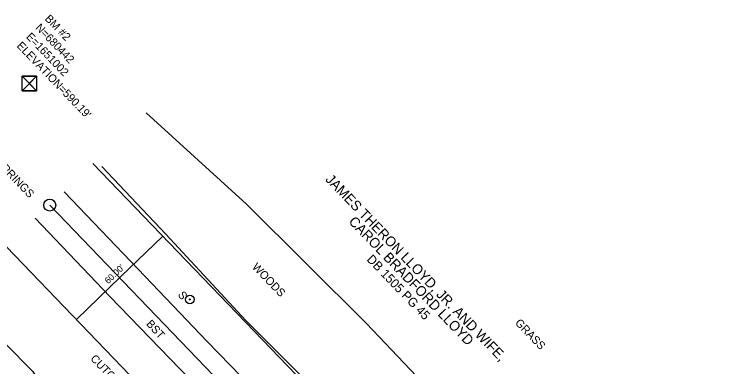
# Model space of a CAD drawing. Extents: x 1650735 to 1651711, y 679647 to 680525.
# Drawn here: x 1650994.6 to 1651353.2, y 680300.3 to 680476.3 of the extents above; entities that cross this region are included whole.
import ezdxf

# ---------------------------------------------------------------- set-up
doc = ezdxf.new("R2010")
doc.units = 0
for name, color, linetype in [('CTL Bench Mark CELL', 7, 'Continuous'), ('CTL Bench Mark Text', 7, 'Continuous'), ('Exist Horizontal Alignment', 7, 'Continuous'), ('Exist Horizontal Alignment Point', 7, 'Continuous'), ('Exist Other Culture Sign CELL', 7, 'Continuous'), ('Exist Other Culture Sign Text', 7, 'Continuous'), ('Exist Property Deed Book Text', 7, 'Continuous'), ('Exist Property Owner Text', 7, 'Continuous'), ('Exist Right of Way Line', 7, 'Continuous'), ('Exist Right of Way Width CELL', 7, 'Continuous'), ('Exist Roads EOP', 7, 'Continuous'), ('Exist Roads EOP Text', 7, 'Continuous'), ('Exist Vegetation Woods Line', 7, 'Continuous'), ('Exist Vegetation Woods Line Text', 7, 'Continuous')]:
    doc.layers.add(name, color=color, linetype=linetype)

msp = doc.modelspace()

# ---------------------------------------------------------------- linework, layer by layer
at = {"layer": 'CTL Bench Mark CELL'}
msp.add_line((1651002.18, 680441.76), (1651002.18, 680441.76), dxfattribs=at)
msp.add_lwpolyline([(1650998.58, 680445.35), (1651005.77, 680445.35), (1651005.77, 680438.16), (1650998.58, 680438.16)], close=True, dxfattribs=at)
for points in [[(1651005.77, 680445.35), (1650998.58, 680438.16), (1651002.17, 680441.75), (1651005.77, 680438.16), (1650998.58, 680445.35)], [(1651002.17, 680441.75), (1651005.77, 680445.35), (1650998.58, 680445.35), (1651002.17, 680441.75)], [(1651002.17, 680441.75), (1650998.58, 680438.16), (1651005.77, 680438.16), (1651002.17, 680441.75)]]:
    msp.add_lwpolyline(points, dxfattribs=at)
at = {"layer": 'Exist Horizontal Alignment'}
msp.add_line((1651012.3, 680380.99), (1651537.82, 679835.25), dxfattribs=at)
at = {"layer": 'Exist Horizontal Alignment Point'}
msp.add_circle((1651012.3, 680380.99), 3, dxfattribs=at)
at = {"layer": 'Exist Other Culture Sign CELL'}
for radius in [2.18, 0.24]:
    msp.add_circle((1651082.34, 680333.82), radius, dxfattribs=at)
at = {"layer": 'Exist Right of Way Line'}
for p, q in [((1651033.91, 680401.8), (1651559.43, 679856.06)), ((1650990.69, 680360.18), (1651516.21, 679814.44))]:
    msp.add_line(p, q, dxfattribs=at)
at = {"layer": 'Exist Right of Way Width CELL'}
for p in [(1651068.86, 680365.51), (1651025.64, 680323.89)]:
    msp.add_line(p, (1651047.86, 680345.28), dxfattribs=at)
at = {"layer": 'Exist Roads EOP'}
for points in [[(1651019.58, 680387.57), (1651056.5, 680349), (1651091.07, 680312.89), (1651125.44, 680277.26), (1651159.55, 680241.49), (1651193.48, 680206.33), (1651231.7, 680167.56), (1651235.09, 680166.23)], [(1651005.03, 680374.4), (1651042.33, 680335.37), (1651077.42, 680299.13), (1651111.45, 680263.82), (1651145.42, 680228.7), (1651180.3, 680192.34), (1651207.92, 680162.35), (1651208.79, 680159.11)]]:
    msp.add_lwpolyline(points, dxfattribs=at)
at = {"layer": 'Exist Vegetation Woods Line'}
for points in [[(1651060.47, 680427.14), (1651110.65, 680381.51), (1651170.59, 680321.84), (1651211.4, 680279.05), (1651264.74, 680217.96)], [(1651268.45, 680153.23), (1651214.56, 680217.23), (1651185.34, 680244.85), (1651142.06, 680291.73), (1651110.43, 680323.33), (1651070.3, 680366.4), (1651038.41, 680400.33)], [(1650967.81, 680302.13), (1650989.98, 680311.82), (1651003.7, 680297.93), (1651028.47, 680259.93), (1651064.77, 680218.76), (1651095.8, 680179.69), (1651142.63, 680135.48), (1651192.79, 680096.42), (1651205.99, 680052.81)]]:
    msp.add_lwpolyline(points, dxfattribs=at)

# ---------------------------------------------------------------- texts
at = {"layer": 'CTL Bench Mark Text'}
for s, p in [('BM #2', (1651009.6, 680473.86)), ('N=680442', (1651004.91, 680469.35)), ('E=1651002', (1651000.23, 680464.84)), ("ELEVATION=590.19'", (1650995.55, 680460.33))]:
    msp.add_text(s, height=4, rotation=313.9188, dxfattribs=at).set_placement(p)
at = {"layer": 'Exist Other Culture Sign Text'}
msp.add_text('S', height=4, rotation=305.7008, dxfattribs=at).set_placement((1651076.13, 680336.19))
at = {"layer": 'Exist Property Deed Book Text'}
msp.add_text('DB 1505 PG 45', height=4.5, rotation=313.9188, dxfattribs=at).set_placement((1651170.44, 680353.57))
at = {"layer": 'Exist Property Owner Text'}
for s, p in [('JAMES THERON LLOYD, JR. AND WIFE,', (1651149.79, 680393.51)), ('CAROL BRADFORD LLOYD', (1651161.4, 680372.44))]:
    msp.add_text(s, height=5, rotation=313.9188, dxfattribs=at).set_placement(p)
at = {"layer": 'Exist Right of Way Width CELL'}
msp.add_text("60.00'", height=3.2, rotation=43.9188, dxfattribs=at).set_placement((1651041.59, 680341.37))
at = {"layer": 'Exist Roads EOP Text'}
for s, rotation, p in [('TO HEALING SPRINGS', 313.9592, (1650961.85, 680426)), ('BST', 312.237, (1651060.28, 680321.44))]:
    msp.add_text(s, height=4, rotation=rotation, dxfattribs=at).set_placement(p)
at = {"layer": 'Exist Vegetation Woods Line Text'}
for s, p in [('WOODS', (1651113.21, 680349.77)), ('GRASS', (1651244.66, 680321.83)), ('CUTOVER', (1651032.38, 680303.96))]:
    msp.add_text(s, height=4, rotation=313.9188, dxfattribs=at).set_placement(p)

doc.saveas('drawing.dxf')
